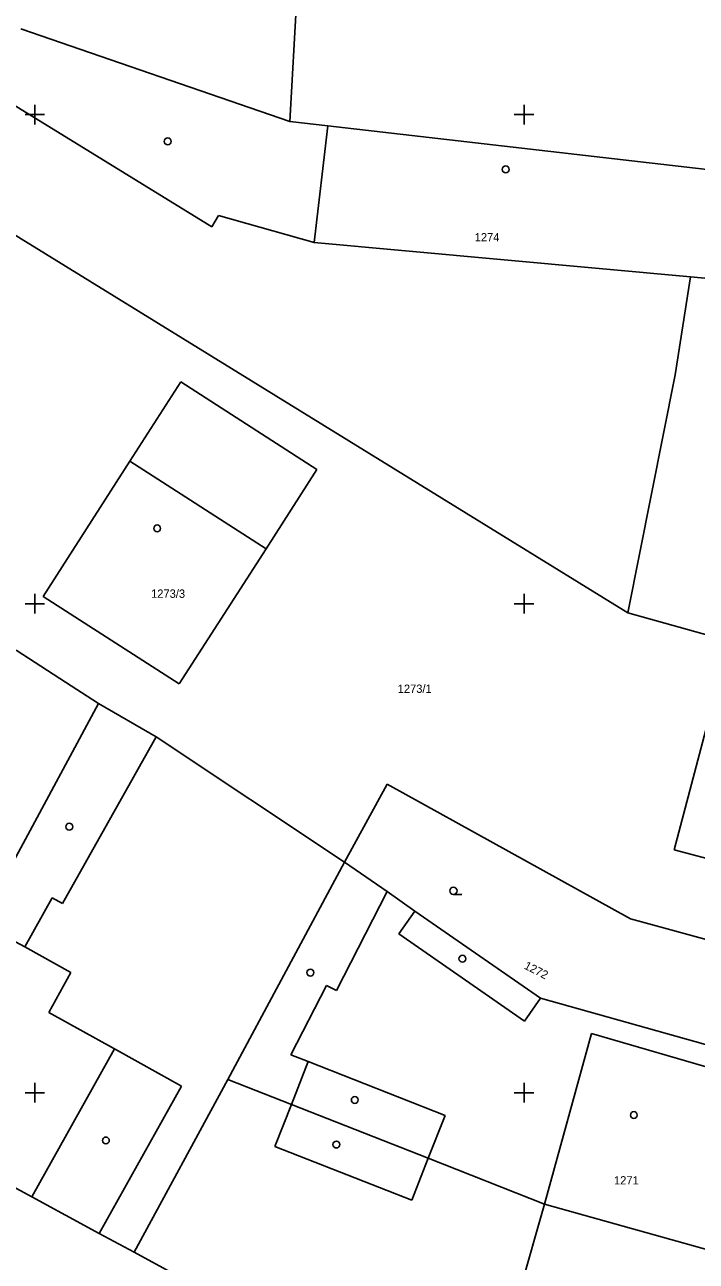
# Model space of a CAD drawing. Extents: x -702257 to -701487, y -1009871 to -1008841.
# Drawn here: x -701800.5 to -701766.2, y -1009358.6 to -1009295.4 of the extents above; entities that cross this region are included whole.
import ezdxf

# ---------------------------------------------------------------- set-up
doc = ezdxf.new("R2010")
doc.units = 0
for name, color, linetype in [('Z_hektometricka_sit', 7, 'Continuous'), ('Z_katastr_cisla_pozemkova', 7, 'Continuous'), ('Z_katastr_cisla_stavebni', 7, 'Continuous'), ('Z_katastr_hranice', 7, 'Continuous'), ('Z_katastr_vnitrni_kresba', 7, 'Continuous'), ('Z_katastr_znacky_budov', 7, 'Continuous'), ('Z_katastr_znacky_kultur', 7, 'Continuous')]:
    doc.layers.add(name, color=color, linetype=linetype)

msp = doc.modelspace()

# ---------------------------------------------------------------- linework, layer by layer
at = {"layer": 'Z_hektometricka_sit'}
for p, q in [((-701800, -1009299.5), (-701800, -1009300.5)), ((-701800, -1009299.5), (-701800, -1009300.5)), ((-701775, -1009299.5), (-701775, -1009300.5)), ((-701775, -1009299.5), (-701775, -1009300.5)), ((-701800.5, -1009300), (-701799.5, -1009300)), ((-701800.5, -1009300), (-701799.5, -1009300)), ((-701775.5, -1009300), (-701774.5, -1009300)), ((-701775.5, -1009300), (-701774.5, -1009300)), ((-701800, -1009324.5), (-701800, -1009325.5)), ((-701800, -1009324.5), (-701800, -1009325.5)), ((-701775, -1009324.5), (-701775, -1009325.5)), ((-701775, -1009324.5), (-701775, -1009325.5)), ((-701800.5, -1009325), (-701799.5, -1009325)), ((-701800.5, -1009325), (-701799.5, -1009325)), ((-701775.5, -1009325), (-701774.5, -1009325)), ((-701775.5, -1009325), (-701774.5, -1009325)), ((-701800.5, -1009350), (-701799.5, -1009350)), ((-701800.5, -1009350), (-701799.5, -1009350)), ((-701800.5, -1009350), (-701799.5, -1009350)), ((-701800, -1009349.5), (-701800, -1009350.5)), ((-701800, -1009349.5), (-701800, -1009350.5)), ((-701800, -1009349.5), (-701800, -1009350.5)), ((-701775.5, -1009350), (-701774.5, -1009350)), ((-701775.5, -1009350), (-701774.5, -1009350)), ((-701775.5, -1009350), (-701774.5, -1009350)), ((-701775, -1009349.5), (-701775, -1009350.5)), ((-701775, -1009349.5), (-701775, -1009350.5)), ((-701775, -1009349.5), (-701775, -1009350.5))]:
    msp.add_line(p, q, dxfattribs=at)
at = {"layer": 'Z_katastr_hranice'}
for p, q in [((-701786.97, -1009300.35), (-701786.42, -1009290.49)), ((-701786.97, -1009300.35), (-701800.71, -1009295.62)), ((-701769.7, -1009325.47), (-701811.94, -1009299.43)), ((-701785.02, -1009300.57), (-701786.97, -1009300.35)), ((-701764.16, -1009302.97), (-701785.02, -1009300.57)), ((-701767.28, -1009313.31), (-701766.49, -1009308.3)), ((-701766.49, -1009308.3), (-701764.85, -1009308.45)), ((-701769.7, -1009325.47), (-701767.28, -1009313.31)), ((-701795.15, -1009317.71), (-701792.53, -1009313.66)), ((-701792.53, -1009313.66), (-701785.59, -1009318.14)), ((-701799.58, -1009324.64), (-701795.15, -1009317.71)), ((-701785.59, -1009318.14), (-701788.17, -1009322.2)), ((-701788.17, -1009322.2), (-701792.63, -1009329.09)), ((-701792.63, -1009329.09), (-701799.58, -1009324.64)), ((-701764.52, -1009326.91), (-701769.7, -1009325.47)), ((-701767.32, -1009337.58), (-701764.52, -1009326.91)), ((-701798.72, -1009328.82), (-701800.96, -1009327.37)), ((-701796.75, -1009330.1), (-701798.72, -1009328.82)), ((-701801.69, -1009339.29), (-701796.75, -1009330.1)), ((-701793.8, -1009331.8), (-701796.75, -1009330.1)), ((-701784.18, -1009338.21), (-701793.8, -1009331.8)), ((-701781.99, -1009334.22), (-701784.18, -1009338.21)), ((-701769.56, -1009341.11), (-701781.99, -1009334.22)), ((-701759.02, -1009339.8), (-701767.32, -1009337.58)), ((-701790.13, -1009349.32), (-701784.18, -1009338.21)), ((-701782, -1009339.72), (-701784.18, -1009338.21)), ((-701780.58, -1009340.71), (-701782, -1009339.72)), ((-701774.15, -1009345.17), (-701780.58, -1009340.71)), ((-701760.07, -1009343.72), (-701769.56, -1009341.11)), ((-701761.54, -1009348.72), (-701774.15, -1009345.17)), ((-701794.93, -1009358.15), (-701790.13, -1009349.32)), ((-701786.89, -1009350.6), (-701790.13, -1009349.32)), ((-701779.9, -1009353.35), (-701786.89, -1009350.6)), ((-701800.15, -1009355.32), (-701808.02, -1009351.06)), ((-701773.96, -1009355.69), (-701779.9, -1009353.35)), ((-701796.71, -1009357.19), (-701800.15, -1009355.32)), ((-701764.34, -1009358.38), (-701773.96, -1009355.69)), ((-701794.93, -1009358.15), (-701796.71, -1009357.19)), ((-701773.66, -1009369.67), (-701794.93, -1009358.15))]:
    msp.add_line(p, q, dxfattribs=at)
at = {"layer": 'Z_katastr_vnitrni_kresba'}
for p, q in [((-701790.96, -1009305.74), (-701801.98, -1009298.95)), ((-701785.02, -1009300.57), (-701785.72, -1009306.54)), ((-701790.61, -1009305.16), (-701790.96, -1009305.74)), ((-701785.72, -1009306.54), (-701790.61, -1009305.16)), ((-701766.49, -1009308.3), (-701785.72, -1009306.54)), ((-701788.17, -1009322.2), (-701795.15, -1009317.71)), ((-701793.8, -1009331.8), (-701798.59, -1009340.33)), ((-701782, -1009339.72), (-701784.58, -1009344.77)), ((-701799.12, -1009340.04), (-701800.51, -1009342.54)), ((-701798.59, -1009340.33), (-701799.12, -1009340.04)), ((-701781.4, -1009341.88), (-701780.58, -1009340.71)), ((-701800.51, -1009342.54), (-701802.79, -1009341.34)), ((-701774.97, -1009346.34), (-701781.4, -1009341.88)), ((-701800.51, -1009342.54), (-701798.16, -1009343.85)), ((-701798.16, -1009343.85), (-701799.29, -1009345.89)), ((-701785.09, -1009344.51), (-701786.91, -1009348.06)), ((-701784.58, -1009344.77), (-701785.09, -1009344.51)), ((-701774.15, -1009345.17), (-701774.97, -1009346.34)), ((-701799.29, -1009345.89), (-701795.93, -1009347.76)), ((-701771.55, -1009346.97), (-701773.96, -1009355.69)), ((-701761.85, -1009349.79), (-701771.55, -1009346.97)), ((-701795.93, -1009347.76), (-701800.15, -1009355.32)), ((-701795.93, -1009347.76), (-701792.51, -1009349.67)), ((-701786.91, -1009348.06), (-701786.03, -1009348.41)), ((-701786.03, -1009348.41), (-701786.89, -1009350.6)), ((-701786.03, -1009348.41), (-701779.03, -1009351.17)), ((-701792.51, -1009349.67), (-701796.71, -1009357.19)), ((-701786.89, -1009350.6), (-701787.73, -1009352.74)), ((-701779.03, -1009351.17), (-701779.9, -1009353.35)), ((-701787.73, -1009352.74), (-701780.74, -1009355.49)), ((-701780.74, -1009355.49), (-701779.9, -1009353.35)), ((-701773.96, -1009355.69), (-701776.4, -1009364.35))]:
    msp.add_line(p, q, dxfattribs=at)
at = {"layer": 'Z_katastr_znacky_budov'}
for centre in [(-701793.207, -1009301.369), (-701775.937, -1009302.799), (-701793.747, -1009321.149), (-701798.237, -1009336.399), (-701778.147, -1009343.149), (-701785.917, -1009343.859), (-701783.647, -1009350.369), (-701769.387, -1009351.139), (-701796.367, -1009352.439), (-701784.587, -1009352.649)]:
    msp.add_circle(centre, 0.175, dxfattribs=at)
at = {"layer": 'Z_katastr_znacky_kultur'}
msp.add_line((-701778.608, -1009339.87), (-701778.171, -1009339.87), dxfattribs=at)
msp.add_circle((-701778.608, -1009339.682), 0.187, dxfattribs=at)

# ---------------------------------------------------------------- texts
at = {"layer": 'Z_katastr_cisla_pozemkova'}
msp.add_text('1273/1', height=0.425, dxfattribs=at).set_placement((-701781.455, -1009329.559))
msp.add_text('1272', height=0.425, rotation=333, dxfattribs=at).set_placement((-701775.033, -1009343.637))
at = {"layer": 'Z_katastr_cisla_stavebni'}
for s, p in [('1274', (-701777.52, -1009306.48)), ('1273/3', (-701794.059, -1009324.7)), ('1271', (-701770.401, -1009354.69))]:
    msp.add_text(s, height=0.425, dxfattribs=at).set_placement(p)

doc.saveas('drawing.dxf')
